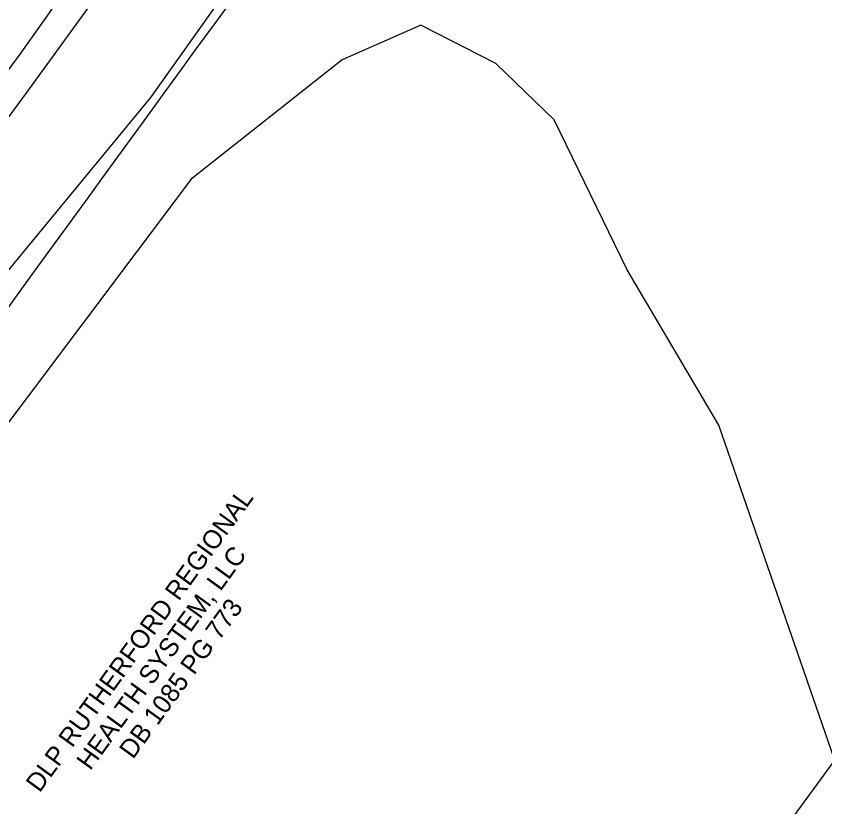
# Model space of a CAD drawing. Extents: x 1182322 to 1186765, y 572295 to 575411.
# Drawn here: x 1184239.9 to 1184456.8, y 573429.7 to 573641.9 of the extents above; entities that cross this region are included whole.
import ezdxf

# ---------------------------------------------------------------- set-up
doc = ezdxf.new("R2010")
doc.units = 0
for name, color, linetype in [('COGO Default Chain', 7, 'Continuous'), ('Exist Guardrail', 7, 'Continuous'), ('Exist Horizontal Alignment', 7, 'Continuous'), ('Exist Property Deed Book Text', 7, 'Continuous'), ('Exist Property Owner Text', 7, 'Continuous'), ('Exist Right of Way Line', 7, 'Continuous'), ('Exist Roads EOP', 7, 'Continuous'), ('Exist Vegetation Woods Line', 7, 'Continuous'), ('Sheet Layout Plan Border', 7, 'Continuous')]:
    doc.layers.add(name, color=color, linetype=linetype)

msp = doc.modelspace()

# ---------------------------------------------------------------- linework, layer by layer
at = {"layer": 'COGO Default Chain'}
msp.add_arc((1124762.27, 616900.03), 73539.16, 323.6095929, 324.1030428, dxfattribs=at)
at = {"layer": 'Exist Guardrail'}
msp.add_lwpolyline([(1184594.84, 573755.66), (1184581.2, 573754.58), (1184547.52, 573751.95), (1184509.98, 573749.08), (1184469.15, 573745.92), (1184435.77, 573743.21), (1184410.17, 573741.05), (1184381.08, 573737.92), (1184359.98, 573734.84), (1184343.19, 573731.95), (1184332.72, 573729), (1184325.59, 573725.67), (1184320.11, 573721.72), (1184312.32, 573714.54), (1184307.06, 573708.76), (1184300.35, 573700.18), (1184274.63, 573665.56), (1184242.6, 573621.44), (1184211.01, 573578.54), (1184178.56, 573533.74), (1184149.85, 573494.36), (1184125.97, 573461.42), (1184110.36, 573439.47)], dxfattribs=at)
at = {"layer": 'Exist Horizontal Alignment'}
msp.add_arc((1124762.27, 616900.03), 73539.16, 323.6095929, 324.1030428, dxfattribs=at)
at = {"layer": 'Exist Right of Way Line'}
msp.add_arc((1124762.27, 616900.03), 73589.16, 323.6095929, 324.0203142, dxfattribs=at)
at = {"layer": 'Exist Roads EOP'}
msp.add_lwpolyline([(1184294.07, 573703.83), (1184290.46, 573699.04), (1184286.84, 573694.25), (1184283.23, 573689.47), (1184279.64, 573684.67), (1184276.06, 573679.86), (1184272.47, 573675.05), (1184268.89, 573670.24), (1184265.26, 573665.46), (1184261.64, 573660.69), (1184258.02, 573655.91), (1184254.53, 573651.03), (1184251.07, 573646.13), (1184247.61, 573641.24), (1184244.15, 573636.34), (1184240.67, 573631.45), (1184237.12, 573626.63)], dxfattribs=at)
at = {"layer": 'Exist Vegetation Woods Line'}
for points in [[(1184428.35, 573532.1), (1184403.72, 573573.78), (1184384.15, 573614.08), (1184368.48, 573629.2), (1184348.41, 573639.47), (1184327.32, 573630.13), (1184286.8, 573598.15), (1184228.4, 573520.48), (1184187.73, 573488.6), (1184178.44, 573486.8), (1184174.62, 573488.17), (1184234.18, 573569.36), (1184276, 573620.06), (1184320.6, 573682.94), (1184353.74, 573705.58), (1184429.72, 573716.26), (1184519.09, 573721.7), (1184575.02, 573729.05)], [(1184463.47, 573430.5), (1184428.35, 573532.1)]]:
    msp.add_lwpolyline(points, dxfattribs=at)
at = {"layer": 'Sheet Layout Plan Border'}
msp.add_line((1184597.69, 573631.02), (1184066.18, 572905.74), dxfattribs=at)

# ---------------------------------------------------------------- texts
at = {"layer": 'Exist Property Deed Book Text'}
msp.add_text('DB 1085 PG 773', height=5, rotation=54.0376, dxfattribs=at).set_placement((1184271.2, 573442.3))
at = {"layer": 'Exist Property Owner Text'}
for s, p in [('DLP RUTHERFORD REGIONAL', (1184246.16, 573433.32)), ('HEALTH SYSTEM, LLC', (1184259.74, 573439.26))]:
    msp.add_text(s, height=5, rotation=54.0376, dxfattribs=at).set_placement(p)

doc.saveas('drawing.dxf')
